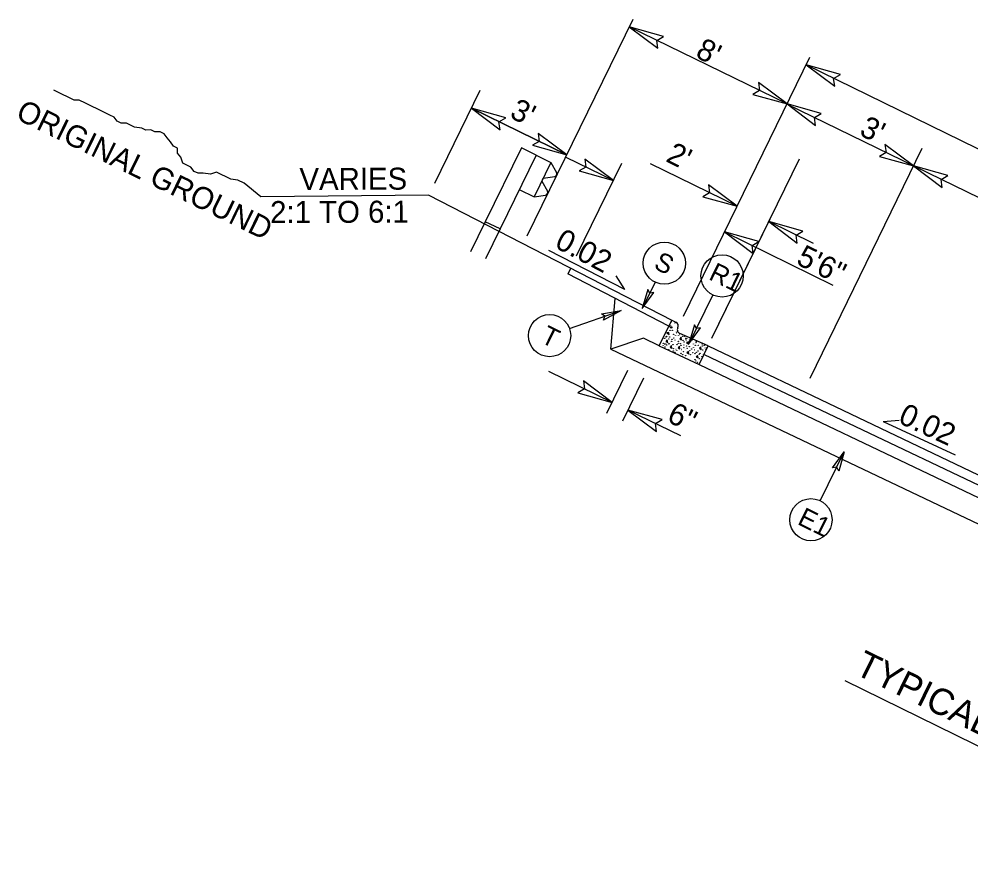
# Model space of a CAD drawing. Extents: x 1518247 to 1523638, y 635234 to 639927.
# Drawn here: x 1522307.5 to 1522739.6, y 636272.6 to 636662 of the extents above; entities that cross this region are included whole.
import ezdxf

# ---------------------------------------------------------------- set-up
doc = ezdxf.new("R2010")
doc.units = 0
for name, color, linetype in [('Prop Dimension', 7, 'Continuous'), ('Prop Dimension Text', 7, 'Continuous'), ('Prop Shade Light', 7, 'Continuous'), ('Typical Arrow Superelevation CELL', 7, 'Continuous'), ('Typical Berm CELL', 7, 'Continuous'), ('Typical Berm Information CELL', 7, 'Continuous'), ('Typical Curb CELL', 7, 'Continuous'), ('Typical Guardrail CELL', 7, 'Continuous'), ('Typical Hinge Slope Arterial CELL', 7, 'Continuous'), ('Typical Hinge Slope Interstate CELL', 7, 'Continuous'), ('Typical ID Circle CELL', 7, 'Continuous'), ('Typical Pavement Slope CELL', 7, 'Continuous'), ('Typical Pavement Slope Information CELL', 7, 'Continuous'), ('Typical Text ID Circle CELL', 7, 'Continuous'), ('Typical Text Label CELL', 7, 'Continuous')]:
    doc.layers.add(name, color=color, linetype=linetype)

# ---------------------------------------------------------------- blocks, each defined once
blk = doc.blocks.new('TERMINATOR')
at = {"layer": 'Prop Shade Light'}
blk.add_lwpolyline([(-0.469, 0.081), (0, 0), (-0.471, -0.083), (-0.411, 0)], close=True, dxfattribs=at)

msp = doc.modelspace()

# ---------------------------------------------------------------- linework, layer by layer
at = {"layer": 'Prop Dimension'}
for p, q in [((1522538.19, 636563.63), (1522586.23, 636662.05)), ((1522656.12, 636623.49), (1522584.48, 636658.47)), ((1522609.1, 636527.16), (1522666.51, 636644.76)), ((1523082.72, 636437.18), (1522664.78, 636641.22)), ((1522496.27, 636587.62), (1522516.9, 636629.73)), ((1522556.15, 636600.42), (1522512.89, 636621.53)), ((1522512.92, 636621.6), (1522556.15, 636600.42)), ((1522865.04, 636521.4), (1522656.09, 636623.41)), ((1522666.59, 636499.11), (1522717.5, 636603.4)), ((1522577.29, 636588.77), (1522555.93, 636599.2)), ((1522560.58, 636554.53), (1522581.15, 636596.66)), ((1522633.47, 636577.09), (1522594.17, 636596.27)), ((1522622.01, 636517.25), (1522661.73, 636598.61)), ((1522622.01, 636517.25), (1522650.74, 636576.12)), ((1522668.1, 636560.18), (1522647.8, 636570.09)), ((1522627.76, 636565.4), (1522676.95, 636541.3)), ((1522576.7, 636488.06), (1522548.06, 636502.04)), ((1522583.76, 636502.52), (1522574.23, 636483)), ((1522590.92, 636499.02), (1522581.39, 636479.5)), ((1522607.87, 636472.85), (1522583.87, 636484.56))]:
    msp.add_line(p, q, dxfattribs=at)
at = {"layer": 'Prop Shade Light'}
for points in [[(1522592.89, 636539.31), (1522590.37, 636530.66), (1522595.71, 636537.99), (1522593.79, 636537.66)], [(1522571.89, 636528.26), (1522580.77, 636529.77), (1522572.88, 636525.31), (1522573.42, 636527.18)], [(1522614.1, 636523.22), (1522611.58, 636514.57), (1522616.92, 636521.9), (1522615, 636521.58)], [(1522676.82, 636458.32), (1522682.1, 636465.62), (1522679.59, 636456.9), (1522678.67, 636458.62)]]:
    msp.add_lwpolyline(points, close=True, dxfattribs=at)
at = {"layer": 'Typical Arrow Superelevation CELL'}
msp.add_line((1522582.5, 636539.3), (1522578.54, 636545.43), dxfattribs=at)
at = {"layer": 'Typical Berm CELL'}
for p, q in [((1522493.56, 636582.09), (1522603.8, 636525.4)), ((1522602.4, 636522.67), (1522556.6, 636546.39))]:
    msp.add_line(p, q, dxfattribs=at)
at = {"layer": 'Typical Berm Information CELL'}
msp.add_line((1522582.5, 636539.3), (1522547.95, 636557.06), dxfattribs=at)
at = {"layer": 'Typical Curb CELL'}
for p, q in [((1522598.09, 636513.69), (1522603.8, 636525.4)), ((1522603.8, 636525.4), (1522605.67, 636524.49)), ((1522603.57, 636521.76), (1522602.74, 636522.56)), ((1522602.74, 636522.56), (1522604, 636522.35)), ((1522604, 636522.35), (1522603.57, 636521.76)), ((1522606.51, 636521.86), (1522606.55, 636521.94)), ((1522602.53, 636519.84), (1522601.53, 636519.66)), ((1522601.53, 636519.66), (1522602.58, 636518.8)), ((1522602.58, 636518.8), (1522602.53, 636519.84)), ((1522608.04, 636517.65), (1522607.4, 636516.95)), ((1522607.4, 636516.95), (1522608.23, 636516.49)), ((1522620.26, 636513.67), (1522607.46, 636519.27)), ((1522608.23, 636516.49), (1522608.04, 636517.65)), ((1522598.09, 636513.69), (1522616.18, 636505.31)), ((1522601.78, 636516.38), (1522601.14, 636515.68)), ((1522601.14, 636515.68), (1522601.98, 636515.22)), ((1522601.98, 636515.22), (1522601.78, 636516.38)), ((1522603.68, 636513.87), (1522603.03, 636513.18)), ((1522603.03, 636513.18), (1522603.88, 636512.71)), ((1522603.88, 636512.71), (1522603.68, 636513.87)), ((1522607.34, 636513.54), (1522606.7, 636512.85)), ((1522606.7, 636512.85), (1522607.54, 636512.38)), ((1522607.54, 636512.38), (1522607.34, 636513.54)), ((1522611.48, 636515.47), (1522610.48, 636515.29)), ((1522610.48, 636515.29), (1522611.52, 636514.43)), ((1522611.52, 636514.43), (1522611.48, 636515.47)), ((1522616.18, 636505.31), (1522620.26, 636513.67)), ((1522616.99, 636513.28), (1522616.35, 636512.59)), ((1522616.35, 636512.59), (1522617.19, 636512.12)), ((1522617.19, 636512.12), (1522616.99, 636513.28)), ((1522611.34, 636511.17), (1522610.7, 636510.48)), ((1522610.7, 636510.48), (1522611.54, 636510.01)), ((1522611.54, 636510.01), (1522611.34, 636511.17)), ((1522615.55, 636509.4), (1522614.91, 636508.71)), ((1522614.91, 636508.71), (1522615.75, 636508.24)), ((1522615.75, 636508.24), (1522615.55, 636509.4))]:
    msp.add_line(p, q, dxfattribs=at)
for centre in [(1522603.24, 636523.08), (1522603.51, 636524.57), (1522605.19, 636524.05), (1522600.62, 636517.1), (1522601.18, 636517.73), (1522601.5, 636518.06), (1522602.43, 636516.77), (1522602.87, 636517.75), (1522602.98, 636520.78), (1522603.92, 636516.68), (1522604.02, 636520.72), (1522604.71, 636518.92), (1522604.73, 636517.29), (1522605.51, 636518.28), (1522605.91, 636519.61), (1522605.96, 636520.03), (1522606.87, 636518.37), (1522607.43, 636519), (1522608.69, 636518.04), (1522609.53, 636518.01), (1522610.02, 636517.04), (1522610.54, 636517.09), (1522599.91, 636513.82), (1522599.94, 636514.84), (1522600.54, 636514.46), (1522600.71, 636513.18), (1522601.1, 636514.51), (1522601.51, 636514.06), (1522602.51, 636514.6), (1522602.63, 636514.9), (1522603.07, 636515.23), (1522603.76, 636515.77), (1522604.33, 636514.27), (1522604.53, 636512.4), (1522605.24, 636516.28), (1522605.66, 636513.26), (1522606.18, 636514.26), (1522606.74, 636514.89), (1522606.8, 636515.73), (1522607.7, 636514.68), (1522607.99, 636513.93), (1522608.89, 636516.17), (1522609.29, 636514.1), (1522609.33, 636512.93), (1522609.42, 636515.51), (1522610.33, 636516.33), (1522610.45, 636513.69), (1522610.74, 636512.52), (1522611.82, 636513.38), (1522611.93, 636516.41), (1522612.87, 636512.31), (1522612.97, 636516.35), (1522613.66, 636514.55), (1522613.68, 636512.92), (1522614.46, 636513.91), (1522614.86, 636515.24), (1522614.91, 636515.66), (1522615.83, 636514), (1522616.39, 636514.63), (1522617.64, 636513.67), (1522617.67, 636514.56), (1522618.63, 636513.94), (1522618.97, 636512.67), (1522619.49, 636512.72), (1522602.44, 636511.95), (1522604.5, 636511.37), (1522605.3, 636510.73), (1522605.69, 636512.06), (1522606.1, 636511.62), (1522607.98, 636510.34), (1522608.19, 636512.06), (1522608.78, 636509.69), (1522609.18, 636511.02), (1522610.1, 636509.25), (1522610.18, 636511.89), (1522611.99, 636511.56), (1522612.19, 636509.69), (1522613.33, 636510.56), (1522614.2, 636511.91), (1522614.39, 636510.13), (1522614.95, 636510.76), (1522615.75, 636511.36), (1522616.21, 636509.8), (1522616.41, 636507.93), (1522616.65, 636510.31), (1522617.54, 636508.79), (1522617.84, 636511.8), (1522618.24, 636509.73), (1522618.37, 636511.14), (1522619.28, 636511.96), (1522614.31, 636507.48), (1522614.75, 636506.82), (1522615.55, 636506.18), (1522615.95, 636507.51)]:
    msp.add_circle(centre, 0.064, dxfattribs=at)
for centre, start, end in [((1522604.83, 636522.77), 333.9793, 63.9793), ((1522608.23, 636521.02), 153.9793, 246.3637)]:
    msp.add_arc(centre, 1.91, start, end, dxfattribs=at)
at = {"layer": 'Typical Guardrail CELL'}
for p, q in [((1522535.56, 636603.52), (1522519.18, 636570.03)), ((1522542.26, 636600.24), (1522535.56, 636603.52)), ((1522542.26, 636600.24), (1522525.88, 636566.75)), ((1522542.26, 636600.24), (1522548.96, 636596.96)), ((1522548.96, 636596.96), (1522541.32, 636581.34)), ((1522548.96, 636596.96), (1522551.52, 636592.32)), ((1522545.45, 636589.78), (1522550.68, 636590.61)), ((1522545.14, 636589.15), (1522544.83, 636588.52)), ((1522544.83, 636588.52), (1522547.39, 636583.88)), ((1522545.14, 636589.15), (1522545.45, 636589.78)), ((1522534.61, 636584.61), (1522541.32, 636581.34)), ((1522541.32, 636581.34), (1522546.55, 636582.16)), ((1522519.18, 636570.03), (1522512.53, 636556.44)), ((1522525.88, 636566.75), (1522519.18, 636570.03)), ((1522525.88, 636566.75), (1522519.23, 636553.16))]:
    msp.add_line(p, q, dxfattribs=at)
for centre, start, end in [((1522550.51, 636591.76), 278.9265, 28.9347), ((1522546.38, 636583.31), 278.9011, 28.9318)]:
    msp.add_arc(centre, 1.16, start, end, dxfattribs=at)
at = {"layer": 'Typical Hinge Slope Interstate CELL'}
for p, q in [((1522493.56, 636582.09), (1522417.34, 636581.37)), ((1522557.94, 636548.99), (1522556.6, 636546.39))]:
    msp.add_line(p, q, dxfattribs=at)
msp.add_lwpolyline([(1522417.34, 636581.37), (1522409.71, 636587.59), (1522406.92, 636588.95), (1522403.68, 636589.39), (1522401.82, 636590.29), (1522399.03, 636591.66), (1522397.17, 636592.56), (1522394.4, 636591.6), (1522391.16, 636592.04), (1522388.85, 636592.02), (1522386.99, 636592.92), (1522385.58, 636594.76), (1522383.73, 636595.67), (1522381.87, 636596.58), (1522380.92, 636599.34), (1522379.51, 636601.18), (1522379.49, 636603.5), (1522377.63, 636604.41), (1522376.22, 636606.24), (1522374.82, 636608.08), (1522373.42, 636609.92), (1522371.56, 636610.83), (1522369.24, 636610.8), (1522367.38, 636611.71), (1522365.07, 636611.68), (1522363.21, 636612.59), (1522359.97, 636613.03), (1522358.11, 636613.93), (1522356.25, 636614.84), (1522353.94, 636614.82), (1522352.08, 636615.72), (1522350.68, 636617.56), (1522348.82, 636618.47), (1522346.96, 636619.38), (1522345.1, 636620.29), (1522343.24, 636621.19), (1522340.45, 636622.56), (1522337.67, 636623.91), (1522334.87, 636625.28), (1522332.56, 636625.25), (1522329.78, 636626.61), (1522326.98, 636627.97), (1522323.27, 636629.79)], dxfattribs=at)
at = {"layer": 'Typical ID Circle CELL'}
for p, q in [((1522596.21, 636542.62), (1522590.37, 636530.66)), ((1522622.45, 636536.84), (1522611.58, 636514.57)), ((1522557.4, 636521.53), (1522580.77, 636529.77)), ((1522671.2, 636443.37), (1522682.1, 636465.62))]:
    msp.add_line(p, q, dxfattribs=at)
for centre in [(1522600.42, 636551.23), (1522626.66, 636545.45), (1522548.36, 636518.35), (1522666.98, 636434.76)]:
    msp.add_circle(centre, 9.59, dxfattribs=at)
at = {"layer": 'Typical Pavement Slope CELL'}
for p, q in [((1522576.19, 636512.13), (1522578.14, 636535.23)), ((1522590.92, 636517.19), (1522576.19, 636512.13)), ((1522598.09, 636513.69), (1522590.92, 636517.19)), ((1522620.26, 636513.67), (1522815.69, 636420.3)), ((1522576.19, 636512.13), (1522807.3, 636402.21)), ((1522618.51, 636509.83), (1522814.01, 636416.68)), ((1522616.18, 636505.31), (1522811.77, 636411.86))]:
    msp.add_line(p, q, dxfattribs=at)
at = {"layer": 'Typical Pavement Slope Information CELL'}
for q in [(1522707.05, 636480), (1522732.44, 636464.21)]:
    msp.add_line((1522699.78, 636479.35), q, dxfattribs=at)
at = {"layer": 'Typical Text Label CELL'}
msp.add_line((1522682.31, 636361.76), (1522864.21, 636272.63), dxfattribs=at)

# ---------------------------------------------------------------- block references
at = {"layer": 'Prop Dimension'}
for p, xscale, yscale, rotation in [((1522584.48, 636658.47), 33.82820784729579, -36.41552511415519, 153.97926941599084), ((1522664.78, 636641.22), 33.82820784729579, -36.41552511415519, 153.97926941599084), ((1522656.12, 636623.49), 33.82820784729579, -36.41552511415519, -26.020730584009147), ((1522656.12, 636623.49), 33.82820784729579, -36.41552511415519, 153.97926941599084), ((1522512.89, 636621.53), 33.82820784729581, -36.41552511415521, 153.9792694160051), ((1522556.15, 636600.42), 33.82820784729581, -36.41552511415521, -26.020730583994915), ((1522713.58, 636595.36), 33.82820784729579, -36.41552511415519, -26.020730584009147), ((1522577.29, 636588.77), 33.82820784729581, -36.415525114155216, -26.02073058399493), ((1522713.58, 636595.36), 33.82820784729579, -36.41552511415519, 153.97926941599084), ((1522633.47, 636577.09), 33.82820784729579, -36.41552511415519, -26.020730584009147), ((1522647.8, 636570.09), 33.82820784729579, -36.41552511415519, 153.97926941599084), ((1522627.76, 636565.4), 33.82820784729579, -36.41552511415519, 153.97926941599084), ((1522576.7, 636488.06), 33.82820784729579, -36.41552511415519, -26.020730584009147), ((1522583.87, 636484.56), 33.82820784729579, -36.41552511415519, 153.97926941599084)]:
    msp.add_blockref('TERMINATOR', p, dxfattribs=dict(at, xscale=xscale, yscale=yscale, rotation=rotation))

# ---------------------------------------------------------------- texts
for s, rotation, p in [("8'", 333.9793, (1522614.07, 636644.94)), ("3'", 333.8962, (1522529.76, 636617.52)), ("3'", 333.9793, (1522688.43, 636609.59)), ("2'", 333.9793, (1522600.64, 636597.63)), ('5\'6"', 333.9793, (1522659.8, 636551.01)), ('6"', 333.9793, (1522601.06, 636479.62))]:
    msp.add_text(s, height=9.969, rotation=rotation, dxfattribs=at).set_placement(p)
at = {"layer": 'Prop Dimension Text'}
msp.add_text('TYPICAL SECTION NO. 4', height=11.9625, rotation=333.8962, dxfattribs=at).set_placement((1522686.27, 636365.1))
at = {"layer": 'Typical Berm Information CELL'}
msp.add_text('0.02', height=9.969, rotation=332.1708, dxfattribs=at).set_placement((1522550.16, 636558.62))
at = {"layer": 'Typical Hinge Slope Arterial CELL'}
for s, height, rotation, p in [('ORIGINAL GROUND', 9.9687, 333.9793, (1522305.52, 636616.97)), ('VARIES', 9.969, 0.2071, (1522434.83, 636584.44)), ('2:1 TO 6:1', 9.969, 0.2071, (1522421.52, 636569.44))]:
    msp.add_text(s, height=height, rotation=rotation, dxfattribs=at).set_placement(p)
at = {"layer": 'Typical Pavement Slope Information CELL'}
msp.add_text('0.02', height=9.969, rotation=335.125, dxfattribs=at).set_placement((1522706.07, 636479.01))
at = {"layer": 'Typical Text ID Circle CELL'}
for s, height, rotation, p in [('S', 8.58, 333.9793, (1522595.13, 636549.08)), ('R1', 8.581, 333.9793, (1522620.13, 636544.13)), ('T', 8.58, 333.9793, (1522543.81, 636515.54)), ('E1', 8.581, 333.8962, (1522660.38, 636432.95))]:
    msp.add_text(s, height=height, rotation=rotation, dxfattribs=at).set_placement(p)

doc.saveas('drawing.dxf')
